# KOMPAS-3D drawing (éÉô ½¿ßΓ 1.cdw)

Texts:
  Casper
  Текст на чертеже
  Размерные надписи
  Шероховатость
  Линия-выноска #1
  Линия-выноска #2
  Линия-выноска #3
  Отклонения формы и база
  Заголовок таблицы
  Ячейка таблицы
  Стрелка вида
  Обозначение изменения
  Фигурная скобка
  Номер узла
  Марка координационной оси
  VRCB
  Выносная надпись
  Обозначение узла
  Марка/позиционное обозначение с линией-выноской
  Марка/позиционное обозначение на линии
  Марка/позиционное обозначение без линии-выноски
  Номер группы
  Р кВт
  Ток, А
  Гр1
  Гр2
  Гр3
  Гр4
  ВА 88-32 (3)
  ВА 47-29 (3)
  ДГУ
  ВРУ (ЩМП-7)
  Гр5
  Гр6
  Гр7
  Щиток ЩО1
  Щиток ЩО2
  Щиток ЩО3
  Щиток ЩР1
  Щиток ЩР2
  Щиток ЩР3
  ВР 32-35 250А
  ВА 47-100(3)
  ВА 47-29 ()
  ВА 47-29 (1)
  ЩАО 1
  ЩАО 2
  ЩАО 3
  ЩАО 4
  ЩГП (ЩРН-12)
  ВВГнгLS 5х16 мм2 скрыто
  в гофр. ПВХ трубе
  ВВГнгLS 5х50 мм2
  ВВГнгLS 5х25 мм2 скрыто
  CONTINUOUS0
Dimensions and other numbers on the sheet: 7; 13.22; 20.2; 5.0; 7.9; 100А; 40А; 20А; 25А; 16А; 1:1; 1; 0; 2; 3; 4; 5; 6; 8; 9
